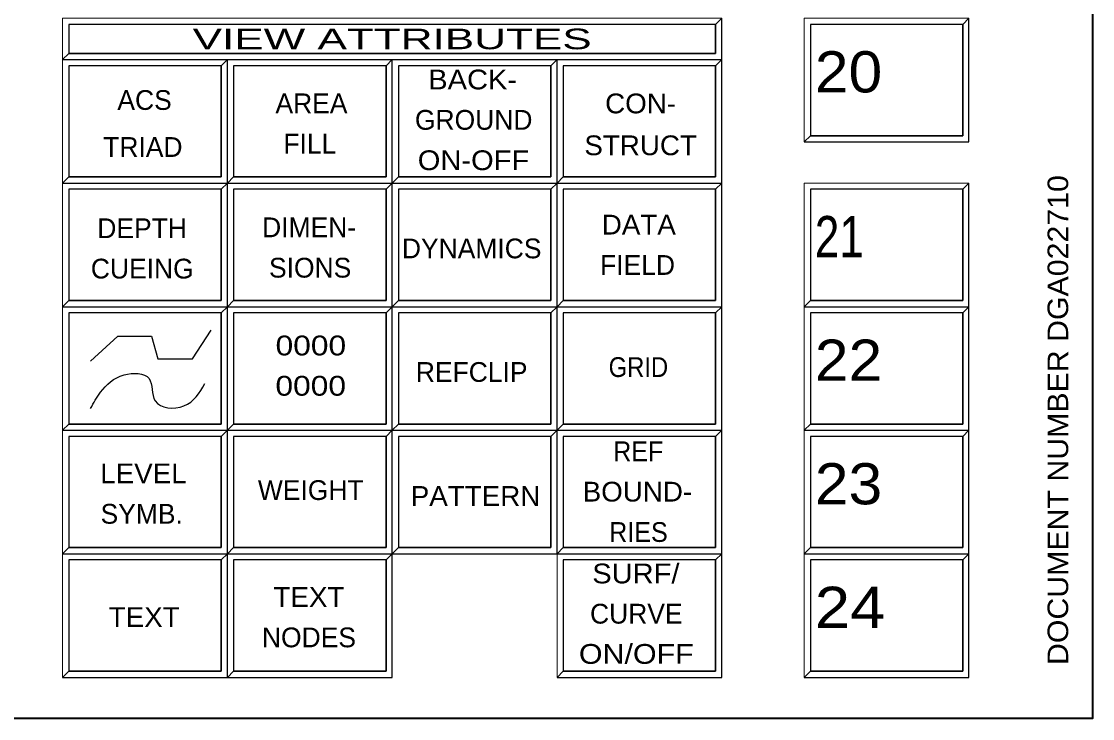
# Model space of a CAD drawing. Extents: x 95906.8 to 95923.6, y 90964.8 to 90972.8.
# Drawn here: x 95916.232 to 95918.832, y 90964.762 to 90966.454 of the extents above; entities that cross this region are included whole.
import ezdxf
from ezdxf.enums import TextEntityAlignment as Align

# ---------------------------------------------------------------- set-up
doc = ezdxf.new("R2010")
doc.units = 0
doc.header["$LTSCALE"] = 0.019
for name, color, linetype, lineweight in [('11', 7, 'Continuous', 25), ('12', 7, 'Continuous', 25), ('2', 7, 'Continuous', 13), ('21', 7, 'Continuous', 25), ('3', 7, 'Continuous', 25), ('6', 7, 'Continuous', 25), ('7', 7, 'Continuous', 35)]:
    doc.layers.add(name, color=color, linetype=linetype, lineweight=lineweight)
doc.layers.add('8', color=7, linetype='Continuous')

msp = doc.modelspace()

# ---------------------------------------------------------------- linework, layer by layer
at = {"layer": '11'}
for points in [[(95918.1473, 90966.1767), (95918.5173, 90966.1767), (95918.5173, 90966.4467), (95918.1473, 90966.4467)], [(95916.3473, 90966.0767), (95916.7173, 90966.0767), (95916.7173, 90966.3467), (95916.3473, 90966.3467)], [(95916.7473, 90966.0767), (95917.1173, 90966.0767), (95917.1173, 90966.3467), (95916.7473, 90966.3467)], [(95917.1473, 90966.0767), (95917.5173, 90966.0767), (95917.5173, 90966.3467), (95917.1473, 90966.3467)], [(95917.5473, 90966.0767), (95917.9173, 90966.0767), (95917.9173, 90966.3467), (95917.5473, 90966.3467)], [(95916.3473, 90965.7767), (95916.7173, 90965.7767), (95916.7173, 90966.0467), (95916.3473, 90966.0467)], [(95916.7473, 90965.7767), (95917.1173, 90965.7767), (95917.1173, 90966.0467), (95916.7473, 90966.0467)], [(95917.1473, 90965.7767), (95917.5173, 90965.7767), (95917.5173, 90966.0467), (95917.1473, 90966.0467)], [(95917.5473, 90965.7767), (95917.9173, 90965.7767), (95917.9173, 90966.0467), (95917.5473, 90966.0467)], [(95918.1473, 90965.7767), (95918.5173, 90965.7767), (95918.5173, 90966.0467), (95918.1473, 90966.0467)], [(95916.3473, 90965.4767), (95916.7173, 90965.4767), (95916.7173, 90965.7467), (95916.3473, 90965.7467)], [(95916.7473, 90965.4767), (95917.1173, 90965.4767), (95917.1173, 90965.7467), (95916.7473, 90965.7467)], [(95917.1473, 90965.4767), (95917.5173, 90965.4767), (95917.5173, 90965.7467), (95917.1473, 90965.7467)], [(95918.1473, 90965.4767), (95918.5173, 90965.4767), (95918.5173, 90965.7467), (95918.1473, 90965.7467)], [(95916.3473, 90965.1767), (95916.7173, 90965.1767), (95916.7173, 90965.4467), (95916.3473, 90965.4467)], [(95916.7473, 90965.1767), (95917.1173, 90965.1767), (95917.1173, 90965.4467), (95916.7473, 90965.4467)], [(95917.1473, 90965.1767), (95917.5173, 90965.1767), (95917.5173, 90965.4467), (95917.1473, 90965.4467)], [(95917.5473, 90965.1767), (95917.9173, 90965.1767), (95917.9173, 90965.4467), (95917.5473, 90965.4467)], [(95918.1473, 90965.1767), (95918.5173, 90965.1767), (95918.5173, 90965.4467), (95918.1473, 90965.4467)], [(95916.3473, 90964.8767), (95916.7173, 90964.8767), (95916.7173, 90965.1467), (95916.3473, 90965.1467)], [(95916.7473, 90964.8767), (95917.1173, 90964.8767), (95917.1173, 90965.1467), (95916.7473, 90965.1467)], [(95917.5473, 90964.8767), (95917.9173, 90964.8767), (95917.9173, 90965.1467), (95917.5473, 90965.1467)], [(95918.1473, 90964.8767), (95918.5173, 90964.8767), (95918.5173, 90965.1467), (95918.1473, 90965.1467)]]:
    msp.add_lwpolyline(points, close=True, dxfattribs=at)
at = {"layer": '12'}
msp.add_lwpolyline([(95917.5473, 90965.4767), (95917.9173, 90965.4767), (95917.9173, 90965.7467), (95917.5473, 90965.7467)], close=True, dxfattribs=at)
at = {"layer": '2'}
for points in [[(95916.3323, 90966.4617), (95916.3323, 90966.3617), (95916.3473, 90966.3767), (95916.3473, 90966.4467), (95917.9173, 90966.4467), (95917.9323, 90966.4617)], [(95918.1323, 90966.4617), (95918.1323, 90966.1617), (95918.1473, 90966.1767), (95918.1473, 90966.4467), (95918.5173, 90966.4467), (95918.5323, 90966.4617)], [(95916.3323, 90966.3617), (95916.3323, 90966.0617), (95916.3473, 90966.0767), (95916.3473, 90966.3467), (95916.7173, 90966.3467), (95916.7323, 90966.3617)], [(95916.7323, 90966.3617), (95916.7323, 90966.0617), (95916.7473, 90966.0767), (95916.7473, 90966.3467), (95917.1173, 90966.3467), (95917.1323, 90966.3617)], [(95917.1323, 90966.3617), (95917.1323, 90966.0617), (95917.1473, 90966.0767), (95917.1473, 90966.3467), (95917.5173, 90966.3467), (95917.5323, 90966.3617)], [(95917.5323, 90966.3617), (95917.5323, 90966.0617), (95917.5473, 90966.0767), (95917.5473, 90966.3467), (95917.9173, 90966.3467), (95917.9323, 90966.3617)], [(95916.3323, 90966.0617), (95916.3323, 90965.7617), (95916.3473, 90965.7767), (95916.3473, 90966.0467), (95916.7173, 90966.0467), (95916.7323, 90966.0617)], [(95916.7323, 90966.0617), (95916.7323, 90965.7617), (95916.7473, 90965.7767), (95916.7473, 90966.0467), (95917.1173, 90966.0467), (95917.1323, 90966.0617)], [(95917.1323, 90966.0617), (95917.1323, 90965.7617), (95917.1473, 90965.7767), (95917.1473, 90966.0467), (95917.5173, 90966.0467), (95917.5323, 90966.0617)], [(95917.5323, 90966.0617), (95917.5323, 90965.7617), (95917.5473, 90965.7767), (95917.5473, 90966.0467), (95917.9173, 90966.0467), (95917.9323, 90966.0617)], [(95918.1323, 90966.0617), (95918.1323, 90965.7617), (95918.1473, 90965.7767), (95918.1473, 90966.0467), (95918.5173, 90966.0467), (95918.5323, 90966.0617)], [(95916.3323, 90965.7617), (95916.3323, 90965.4617), (95916.3473, 90965.4767), (95916.3473, 90965.7467), (95916.7173, 90965.7467), (95916.7323, 90965.7617)], [(95916.7323, 90965.7617), (95916.7323, 90965.4617), (95916.7473, 90965.4767), (95916.7473, 90965.7467), (95917.1173, 90965.7467), (95917.1323, 90965.7617)], [(95917.1323, 90965.7617), (95917.1323, 90965.4617), (95917.1473, 90965.4767), (95917.1473, 90965.7467), (95917.5173, 90965.7467), (95917.5323, 90965.7617)], [(95917.5323, 90965.7617), (95917.5323, 90965.4617), (95917.5473, 90965.4767), (95917.5473, 90965.7467), (95917.9173, 90965.7467), (95917.9323, 90965.7617)], [(95918.1323, 90965.7617), (95918.1323, 90965.4617), (95918.1473, 90965.4767), (95918.1473, 90965.7467), (95918.5173, 90965.7467), (95918.5323, 90965.7617)], [(95916.3323, 90965.4617), (95916.3323, 90965.1617), (95916.3473, 90965.1767), (95916.3473, 90965.4467), (95916.7173, 90965.4467), (95916.7323, 90965.4617)], [(95916.7323, 90965.4617), (95916.7323, 90965.1617), (95916.7473, 90965.1767), (95916.7473, 90965.4467), (95917.1173, 90965.4467), (95917.1323, 90965.4617)], [(95917.1323, 90965.4617), (95917.1323, 90965.1617), (95917.1473, 90965.1767), (95917.1473, 90965.4467), (95917.5173, 90965.4467), (95917.5323, 90965.4617)], [(95917.5323, 90965.4617), (95917.5323, 90965.1617), (95917.5473, 90965.1767), (95917.5473, 90965.4467), (95917.9173, 90965.4467), (95917.9323, 90965.4617)], [(95918.1323, 90965.4617), (95918.1323, 90965.1617), (95918.1473, 90965.1767), (95918.1473, 90965.4467), (95918.5173, 90965.4467), (95918.5323, 90965.4617)], [(95916.3323, 90965.1617), (95916.3323, 90964.8617), (95916.3473, 90964.8767), (95916.3473, 90965.1467), (95916.7173, 90965.1467), (95916.7323, 90965.1617)], [(95916.7323, 90965.1617), (95916.7323, 90964.8617), (95916.7473, 90964.8767), (95916.7473, 90965.1467), (95917.1173, 90965.1467), (95917.1323, 90965.1617)], [(95917.5323, 90965.1617), (95917.5323, 90964.8617), (95917.5473, 90964.8767), (95917.5473, 90965.1467), (95917.9173, 90965.1467), (95917.9323, 90965.1617)], [(95918.1323, 90965.1617), (95918.1323, 90964.8617), (95918.1473, 90964.8767), (95918.1473, 90965.1467), (95918.5173, 90965.1467), (95918.5323, 90965.1617)]]:
    msp.add_lwpolyline(points, close=True, dxfattribs=at)
at = {"layer": '21'}
msp.add_lwpolyline([(95916.3473, 90966.3767), (95917.9173, 90966.3767), (95917.9173, 90966.4467), (95916.3473, 90966.4467)], close=True, dxfattribs=at)
at = {"layer": '3'}
for points in [[(95916.3323, 90966.3617), (95917.9323, 90966.3617), (95917.9323, 90966.4617), (95917.9173, 90966.4467), (95917.9173, 90966.3767), (95916.3473, 90966.3767)], [(95918.1323, 90966.1617), (95918.5323, 90966.1617), (95918.5323, 90966.4617), (95918.5173, 90966.4467), (95918.5173, 90966.1767), (95918.1473, 90966.1767)], [(95916.3323, 90966.0617), (95916.7323, 90966.0617), (95916.7323, 90966.3617), (95916.7173, 90966.3467), (95916.7173, 90966.0767), (95916.3473, 90966.0767)], [(95916.7323, 90966.0617), (95917.1323, 90966.0617), (95917.1323, 90966.3617), (95917.1173, 90966.3467), (95917.1173, 90966.0767), (95916.7473, 90966.0767)], [(95917.1323, 90966.0617), (95917.5323, 90966.0617), (95917.5323, 90966.3617), (95917.5173, 90966.3467), (95917.5173, 90966.0767), (95917.1473, 90966.0767)], [(95917.5323, 90966.0617), (95917.9323, 90966.0617), (95917.9323, 90966.3617), (95917.9173, 90966.3467), (95917.9173, 90966.0767), (95917.5473, 90966.0767)], [(95916.3323, 90965.7617), (95916.7323, 90965.7617), (95916.7323, 90966.0617), (95916.7173, 90966.0467), (95916.7173, 90965.7767), (95916.3473, 90965.7767)], [(95916.7323, 90965.7617), (95917.1323, 90965.7617), (95917.1323, 90966.0617), (95917.1173, 90966.0467), (95917.1173, 90965.7767), (95916.7473, 90965.7767)], [(95917.1323, 90965.7617), (95917.5323, 90965.7617), (95917.5323, 90966.0617), (95917.5173, 90966.0467), (95917.5173, 90965.7767), (95917.1473, 90965.7767)], [(95917.5323, 90965.7617), (95917.9323, 90965.7617), (95917.9323, 90966.0617), (95917.9173, 90966.0467), (95917.9173, 90965.7767), (95917.5473, 90965.7767)], [(95918.1323, 90965.7617), (95918.5323, 90965.7617), (95918.5323, 90966.0617), (95918.5173, 90966.0467), (95918.5173, 90965.7767), (95918.1473, 90965.7767)], [(95916.3323, 90965.4617), (95916.7323, 90965.4617), (95916.7323, 90965.7617), (95916.7173, 90965.7467), (95916.7173, 90965.4767), (95916.3473, 90965.4767)], [(95916.7323, 90965.4617), (95917.1323, 90965.4617), (95917.1323, 90965.7617), (95917.1173, 90965.7467), (95917.1173, 90965.4767), (95916.7473, 90965.4767)], [(95917.1323, 90965.4617), (95917.5323, 90965.4617), (95917.5323, 90965.7617), (95917.5173, 90965.7467), (95917.5173, 90965.4767), (95917.1473, 90965.4767)], [(95917.5323, 90965.4617), (95917.9323, 90965.4617), (95917.9323, 90965.7617), (95917.9173, 90965.7467), (95917.9173, 90965.4767), (95917.5473, 90965.4767)], [(95918.1323, 90965.4617), (95918.5323, 90965.4617), (95918.5323, 90965.7617), (95918.5173, 90965.7467), (95918.5173, 90965.4767), (95918.1473, 90965.4767)], [(95916.3323, 90965.1617), (95916.7323, 90965.1617), (95916.7323, 90965.4617), (95916.7173, 90965.4467), (95916.7173, 90965.1767), (95916.3473, 90965.1767)], [(95916.7323, 90965.1617), (95917.1323, 90965.1617), (95917.1323, 90965.4617), (95917.1173, 90965.4467), (95917.1173, 90965.1767), (95916.7473, 90965.1767)], [(95917.1323, 90965.1617), (95917.5323, 90965.1617), (95917.5323, 90965.4617), (95917.5173, 90965.4467), (95917.5173, 90965.1767), (95917.1473, 90965.1767)], [(95917.5323, 90965.1617), (95917.9323, 90965.1617), (95917.9323, 90965.4617), (95917.9173, 90965.4467), (95917.9173, 90965.1767), (95917.5473, 90965.1767)], [(95918.1323, 90965.1617), (95918.5323, 90965.1617), (95918.5323, 90965.4617), (95918.5173, 90965.4467), (95918.5173, 90965.1767), (95918.1473, 90965.1767)], [(95916.3323, 90964.8617), (95916.7323, 90964.8617), (95916.7323, 90965.1617), (95916.7173, 90965.1467), (95916.7173, 90964.8767), (95916.3473, 90964.8767)], [(95916.7323, 90964.8617), (95917.1323, 90964.8617), (95917.1323, 90965.1617), (95917.1173, 90965.1467), (95917.1173, 90964.8767), (95916.7473, 90964.8767)], [(95917.5323, 90964.8617), (95917.9323, 90964.8617), (95917.9323, 90965.1617), (95917.9173, 90965.1467), (95917.9173, 90964.8767), (95917.5473, 90964.8767)], [(95918.1323, 90964.8617), (95918.5323, 90964.8617), (95918.5323, 90965.1617), (95918.5173, 90965.1467), (95918.5173, 90964.8767), (95918.1473, 90964.8767)]]:
    msp.add_lwpolyline(points, close=True, dxfattribs=at)
at = {"layer": '6'}
msp.add_lwpolyline([(95916.4001, 90965.6293), (95916.4665, 90965.6897), (95916.548, 90965.6897), (95916.5631, 90965.6354), (95916.6477, 90965.6354), (95916.6929, 90965.7048)], dxfattribs=at)
msp.add_spline([(95916.4001, 90965.5146), (95916.4243, 90965.5538), (95916.4816, 90965.5961), (95916.542, 90965.5871), (95916.5571, 90965.5327), (95916.6265, 90965.5206), (95916.6778, 90965.575)], degree=3, dxfattribs=at)
at = {"layer": '7'}
msp.add_lwpolyline([(95906.8323, 90972.7617), (95918.8323, 90972.7617), (95918.8323, 90964.7617), (95906.8323, 90964.7617)], close=True, dxfattribs=at)

# ---------------------------------------------------------------- texts
at = {"layer": '21', "width": 1.6}
msp.add_text('    VIEW ATTRIBUTES    ', height=0.04999, dxfattribs=at).set_placement((95917.1322, 90966.3867), align=Align.CENTER)
at = {"layer": '6'}
for s, width, p in [('20', 1.1, (95918.1581, 90966.2818)), ('21', 0.8, (95918.1581, 90965.8818)), ('22', 1.1, (95918.1581, 90965.5818)), ('23', 1.1, (95918.1581, 90965.2818)), ('24', 1.15, (95918.1581, 90964.9818))]:
    msp.add_text(s, height=0.1, dxfattribs=dict(at, width=width)).set_placement(p)
for s, height, width, p in [('BACK-', 0.048, 1.1, (95917.3276, 90966.2892)), ('CON-', 0.048, 1.05, (95917.7352, 90966.2311)), ('STRUCT', 0.048, 1.05, (95917.7353, 90966.1294)), ('ON-OFF', 0.048, 1.1, (95917.3296, 90966.0932)), ('DATA', 0.048, 1.05, (95917.7309, 90965.9369)), ('0000', 0.048, 1.2, (95916.9348, 90965.6434)), ('GRID', 0.048, 0.9, (95917.7299, 90965.591)), ('0000', 0.048, 1.2, (95916.9345, 90965.5456)), ('REF', 0.04799, 0.95, (95917.7296, 90965.3866)), ('LEVEL', 0.048, 1.05, (95916.5285, 90965.3328)), ('PATTERN', 0.048, 1.05, (95917.3346, 90965.2781)), ('BOUND-', 0.04799, 1.05, (95917.7275, 90965.2886)), ('RIES', 0.04799, 0.95, (95917.73, 90965.1906)), ('SURF/', 0.04799, 1.1, (95917.7238, 90965.0899)), ('TEXT', 0.048, 1.05, (95916.9302, 90965.0328)), ('TEXT', 0.048, 1.05, (95916.5303, 90964.984)), ('ON/OFF', 0.04799, 1.15, (95917.7248, 90964.8947))]:
    msp.add_text(s, height=height, dxfattribs=dict(at, width=width)).set_placement(p, align=Align.CENTER)
for s, height, p in [('ACS', 0.048, (95916.5312, 90966.2394)), ('AREA', 0.048, (95916.9363, 90966.2313)), ('GROUND', 0.048, (95917.3301, 90966.1912)), ('FILL', 0.048, (95916.9324, 90966.1333)), ('TRIAD', 0.048, (95916.5271, 90966.1253)), ('DEPTH', 0.048, (95916.5252, 90965.9281)), ('DIMEN-', 0.048, (95916.9306, 90965.9303)), ('DYNAMICS', 0.048, (95917.3252, 90965.8791)), ('CUEING', 0.048, (95916.5256, 90965.8301)), ('SIONS', 0.048, (95916.9331, 90965.8323)), ('FIELD', 0.048, (95917.7278, 90965.8389)), ('REFCLIP', 0.04799, (95917.3252, 90965.5791)), ('WEIGHT', 0.048, (95916.9346, 90965.2924)), ('SYMB.', 0.048, (95916.5243, 90965.2348)), ('CURVE', 0.04799, (95917.7248, 90964.9923)), ('NODES', 0.048, (95916.9302, 90964.9348))]:
    msp.add_text(s, height=height, dxfattribs=at).set_placement(p, align=Align.CENTER)
at = {"layer": '8', "width": 1.1}
msp.add_text('DOCUMENT NUMBER DGA022710', height=0.05, rotation=90, dxfattribs=at).set_placement((95918.7731, 90965.4863), align=Align.CENTER)

doc.saveas('drawing.dxf')
